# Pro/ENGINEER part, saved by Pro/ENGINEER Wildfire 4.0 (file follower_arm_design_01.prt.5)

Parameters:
  METRIC = "NO"

Other parameters: PITCH, DRILL_DIAMETER, THREAD_DIAMETER, THREADS_PER_INCH, THREAD_DEPTH, THREAD_LENGTH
